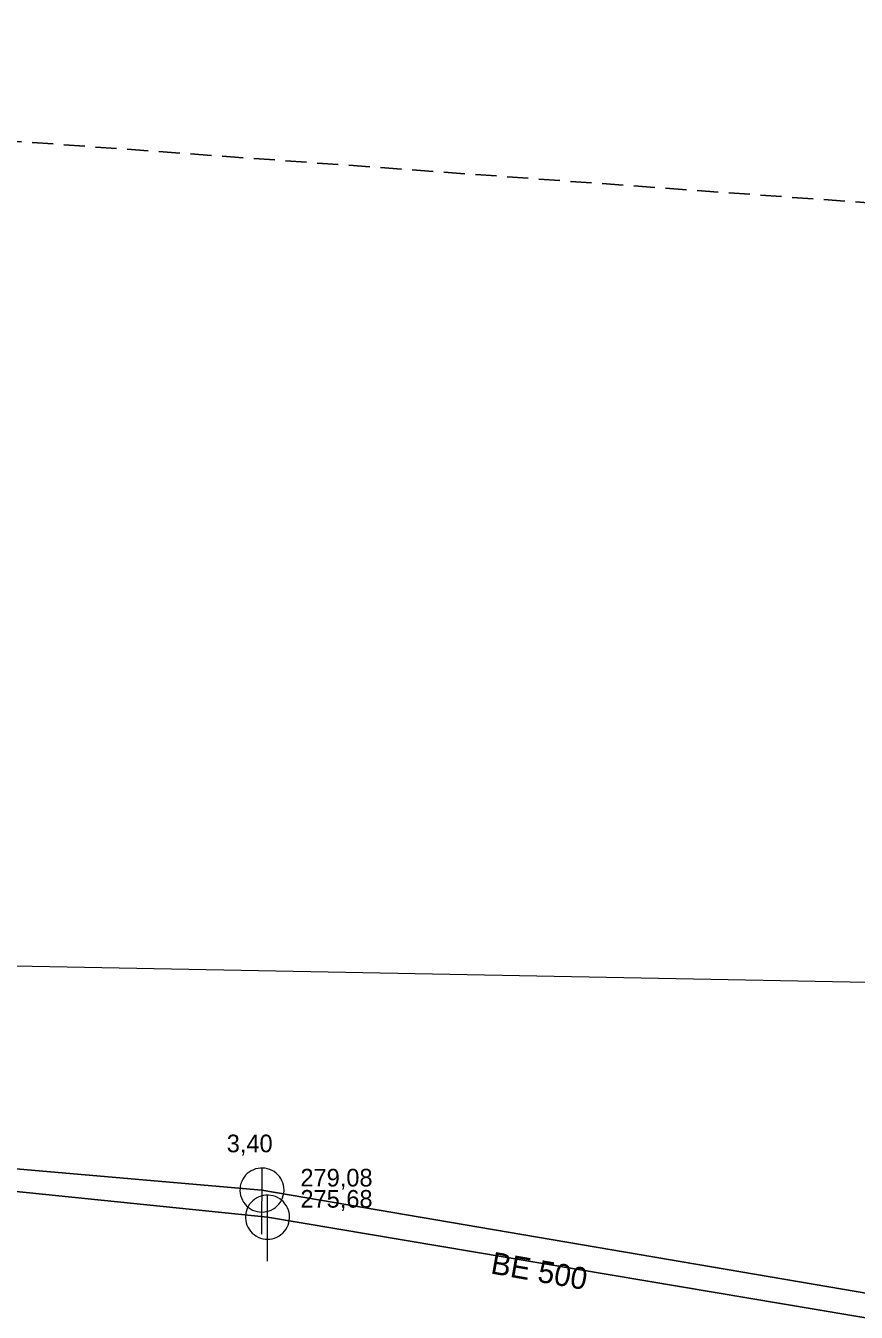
# Model space of a CAD drawing. Extents: x -725153 to -724843, y -978146 to -977794.
# Drawn here: x -725053.1 to -725015.4, y -977852.8 to -977794.5 of the extents above; entities that cross this region are included whole.
import ezdxf

# ---------------------------------------------------------------- set-up
doc = ezdxf.new("R2010")
doc.units = 0
doc.header["$LTSCALE"] = 0.32
doc.linetypes.add('MEDIUM_DASHED', pattern=[4.5, 3, -1.5])
doc.layers.add('1', color=7, linetype='Continuous')
for name, color, linetype, lineweight in [('13', 7, 'Continuous', 13), ('14', 7, 'Continuous', 25), ('22', 7, 'Continuous', 13), ('63', 7, 'MEDIUM_DASHED', 25)]:
    doc.layers.add(name, color=color, linetype=linetype, lineweight=lineweight)

msp = doc.modelspace()

# ---------------------------------------------------------------- linework, layer by layer
at = {"layer": '13'}
msp.add_line((-725010.03, -977837.91), (-725080.007, -977836.588), dxfattribs=at)
at = {"layer": '14'}
for p, q in [((-725081.757, -977843.815), (-725042.36, -977847.23)), ((-725080.73, -977844.53), (-725042.11, -977848.46)), ((-725042.36, -977847.23), (-725013.07, -977852.23)), ((-725042.11, -977848.46), (-725013.14, -977853.34))]:
    msp.add_line(p, q, dxfattribs=at)
at = {"layer": '22'}
for p, q in [((-725042.36, -977849.23), (-725042.359, -977846.23)), ((-725042.11, -977850.46), (-725042.109, -977847.46))]:
    msp.add_line(p, q, dxfattribs=at)
for points in [[(-725041.36, -977847.23), (-725041.365, -977847.121), (-725041.383, -977847.013), (-725041.413, -977846.907), (-725041.453, -977846.806), (-725041.505, -977846.709), (-725041.567, -977846.619), (-725041.639, -977846.536), (-725041.719, -977846.462), (-725041.807, -977846.396), (-725041.901, -977846.341), (-725042.001, -977846.296), (-725042.106, -977846.263), (-725042.213, -977846.241), (-725042.322, -977846.231), (-725042.432, -977846.233), (-725042.54, -977846.247), (-725042.647, -977846.272), (-725042.75, -977846.309), (-725042.848, -977846.358), (-725042.94, -977846.416), (-725043.026, -977846.485), (-725043.103, -977846.562), (-725043.172, -977846.648), (-725043.231, -977846.74), (-725043.279, -977846.838), (-725043.316, -977846.941), (-725043.342, -977847.048), (-725043.356, -977847.156), (-725043.359, -977847.266), (-725043.349, -977847.375), (-725043.328, -977847.482), (-725043.294, -977847.586), (-725043.25, -977847.686), (-725043.195, -977847.781), (-725043.129, -977847.869), (-725043.055, -977847.949), (-725042.972, -977848.021), (-725042.882, -977848.083), (-725042.786, -977848.135), (-725042.684, -977848.176), (-725042.579, -977848.206), (-725042.471, -977848.224), (-725042.361, -977848.23), (-725042.252, -977848.224), (-725042.144, -977848.206), (-725042.039, -977848.177), (-725041.937, -977848.136), (-725041.84, -977848.084), (-725041.75, -977848.022), (-725041.667, -977847.951), (-725041.592, -977847.871), (-725041.527, -977847.783), (-725041.471, -977847.689), (-725041.427, -977847.589), (-725041.393, -977847.485), (-725041.371, -977847.377), (-725041.361, -977847.268)], [(-725041.11, -977848.46), (-725041.115, -977848.351), (-725041.133, -977848.243), (-725041.163, -977848.137), (-725041.203, -977848.036), (-725041.255, -977847.939), (-725041.317, -977847.849), (-725041.389, -977847.766), (-725041.469, -977847.692), (-725041.557, -977847.626), (-725041.651, -977847.571), (-725041.751, -977847.526), (-725041.856, -977847.493), (-725041.963, -977847.471), (-725042.072, -977847.461), (-725042.182, -977847.463), (-725042.29, -977847.477), (-725042.397, -977847.502), (-725042.5, -977847.539), (-725042.598, -977847.588), (-725042.69, -977847.646), (-725042.776, -977847.715), (-725042.853, -977847.792), (-725042.922, -977847.878), (-725042.981, -977847.97), (-725043.029, -977848.068), (-725043.066, -977848.171), (-725043.092, -977848.278), (-725043.106, -977848.386), (-725043.109, -977848.496), (-725043.099, -977848.605), (-725043.078, -977848.712), (-725043.044, -977848.816), (-725043, -977848.916), (-725042.945, -977849.011), (-725042.879, -977849.099), (-725042.805, -977849.179), (-725042.722, -977849.251), (-725042.632, -977849.313), (-725042.536, -977849.365), (-725042.434, -977849.406), (-725042.329, -977849.436), (-725042.221, -977849.454), (-725042.111, -977849.46), (-725042.002, -977849.454), (-725041.894, -977849.436), (-725041.789, -977849.407), (-725041.687, -977849.366), (-725041.59, -977849.314), (-725041.5, -977849.252), (-725041.417, -977849.181), (-725041.342, -977849.101), (-725041.277, -977849.013), (-725041.221, -977848.919), (-725041.177, -977848.819), (-725041.143, -977848.715), (-725041.121, -977848.607), (-725041.111, -977848.498)]]:
    msp.add_lwpolyline(points, close=True, dxfattribs=at)
at = {"layer": '63'}
msp.add_lwpolyline([(-725126.038, -977904.704), (-725126.038, -977794.451), (-724874.829, -977812.594), (-724855.29, -977827.945), (-724842.73, -977919.358), (-724859.477, -977998.21), (-724911.114, -978092.413), (-724961.356, -978146.144), (-725152.554, -978126.605)], close=True, dxfattribs=at)

# ---------------------------------------------------------------- texts
at = {"layer": '1'}
msp.add_text('3,40', height=0.8, dxfattribs=at).set_placement((-725043.959, -977845.518))
msp.add_text('BE 500', height=1, rotation=350, dxfattribs=at).set_placement((-725032.029, -977851.007))
at = {"layer": '22'}
for s, p in [('279,08', (-725040.617, -977847.069)), ('275,68', (-725040.617, -977848.029))]:
    msp.add_text(s, height=0.8, dxfattribs=at).set_placement(p)

doc.saveas('drawing.dxf')
